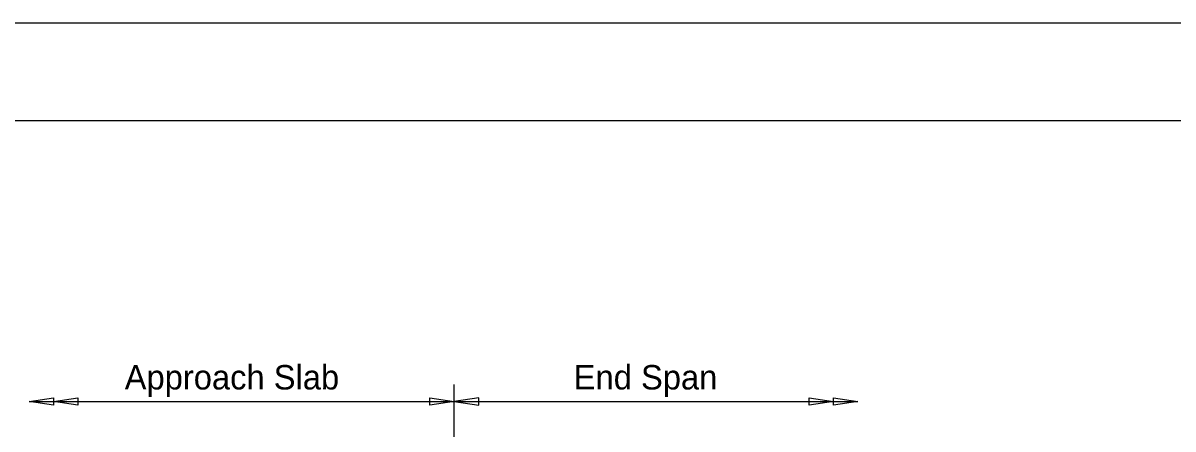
# Model space of a CAD drawing. Extents: x 2799.7 to 2896, y 515.2 to 573.9.
# Drawn here: x 2851.55 to 2867.23, y 568.36 to 573.89 of the extents above; entities that cross this region are included whole.
import ezdxf

# ---------------------------------------------------------------- set-up
doc = ezdxf.new("R2010")
doc.units = 0
for name, color, linetype in [('BR_AUTO DIMENSION', 7, 'Continuous'), ('BR_BORDER LINES', 7, 'Continuous'), ('BR_TEXT', 7, 'Continuous'), ('Level 31', 7, 'Continuous')]:
    doc.layers.add(name, color=color, linetype=linetype)

# ---------------------------------------------------------------- blocks, each defined once
blk = doc.blocks.new('B')
at = {"layer": 'BR_AUTO DIMENSION'}
blk.add_lwpolyline([(-0.2, 0.03), (0, 0), (-0.2, -0.03)], close=True, dxfattribs=at)
blk = doc.blocks.new('ARROW')
at = {"layer": 'BR_AUTO DIMENSION', "xscale": 0.625, "yscale": 0.625}
blk.add_blockref('B', (0, 0), dxfattribs=at)
blk = doc.blocks.new('DAH')
at = {"layer": 'BR_AUTO DIMENSION'}
for p in [(-0.1248, 0), (0, 0)]:
    blk.add_blockref('ARROW', p, dxfattribs=at)

msp = doc.modelspace()

# ---------------------------------------------------------------- linework, layer by layer
at = {"layer": 'BR_AUTO DIMENSION'}
for p, q in [((2857.435, 564.972), (2857.435, 568.962)), ((2851.638, 568.728), (2862.938, 568.728))]:
    msp.add_line(p, q, dxfattribs=at)
for points in [[(2857.102, 568.778), (2857.435, 568.728), (2857.102, 568.678)], [(2857.768, 568.778), (2857.435, 568.728), (2857.768, 568.678)]]:
    msp.add_lwpolyline(points, close=True, dxfattribs=at)
at = {"layer": 'BR_BORDER LINES'}
msp.add_line((2894.359, 572.556), (2804.582, 572.556), dxfattribs=at)
at = {"layer": 'Level 31'}
msp.add_lwpolyline([(2799.693, 515.223), (2895.694, 515.223), (2895.694, 573.89), (2799.693, 573.89)], close=True, dxfattribs=at)

# ---------------------------------------------------------------- block references
at = {"layer": 'BR_AUTO DIMENSION', "xscale": 2.6668000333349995, "yscale": 2.6668000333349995, "rotation": 180}
msp.add_blockref('DAH', (2851.638, 568.728), dxfattribs=at)
at = {"layer": 'BR_AUTO DIMENSION', "xscale": 2.6668000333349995, "yscale": 2.6668000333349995}
msp.add_blockref('DAH', (2862.938, 568.728), dxfattribs=at)

# ---------------------------------------------------------------- texts
at = {"layer": 'BR_TEXT'}
for s, height, p in [('Approach Slab', 0.33332, (2852.941, 568.894)), ('End Span', 0.3333, (2859.063, 568.894))]:
    msp.add_text(s, height=height, dxfattribs=at).set_placement(p)

doc.saveas('drawing.dxf')
